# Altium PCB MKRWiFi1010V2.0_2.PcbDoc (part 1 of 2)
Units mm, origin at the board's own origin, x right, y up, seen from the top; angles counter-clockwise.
Board outline 61.5 x 25 mm, 4 copper layers (Top, PWR, MID, Bottom), stack 0.925 mm thick; 118 components, 85 nets, 439 pads, 197 vias.
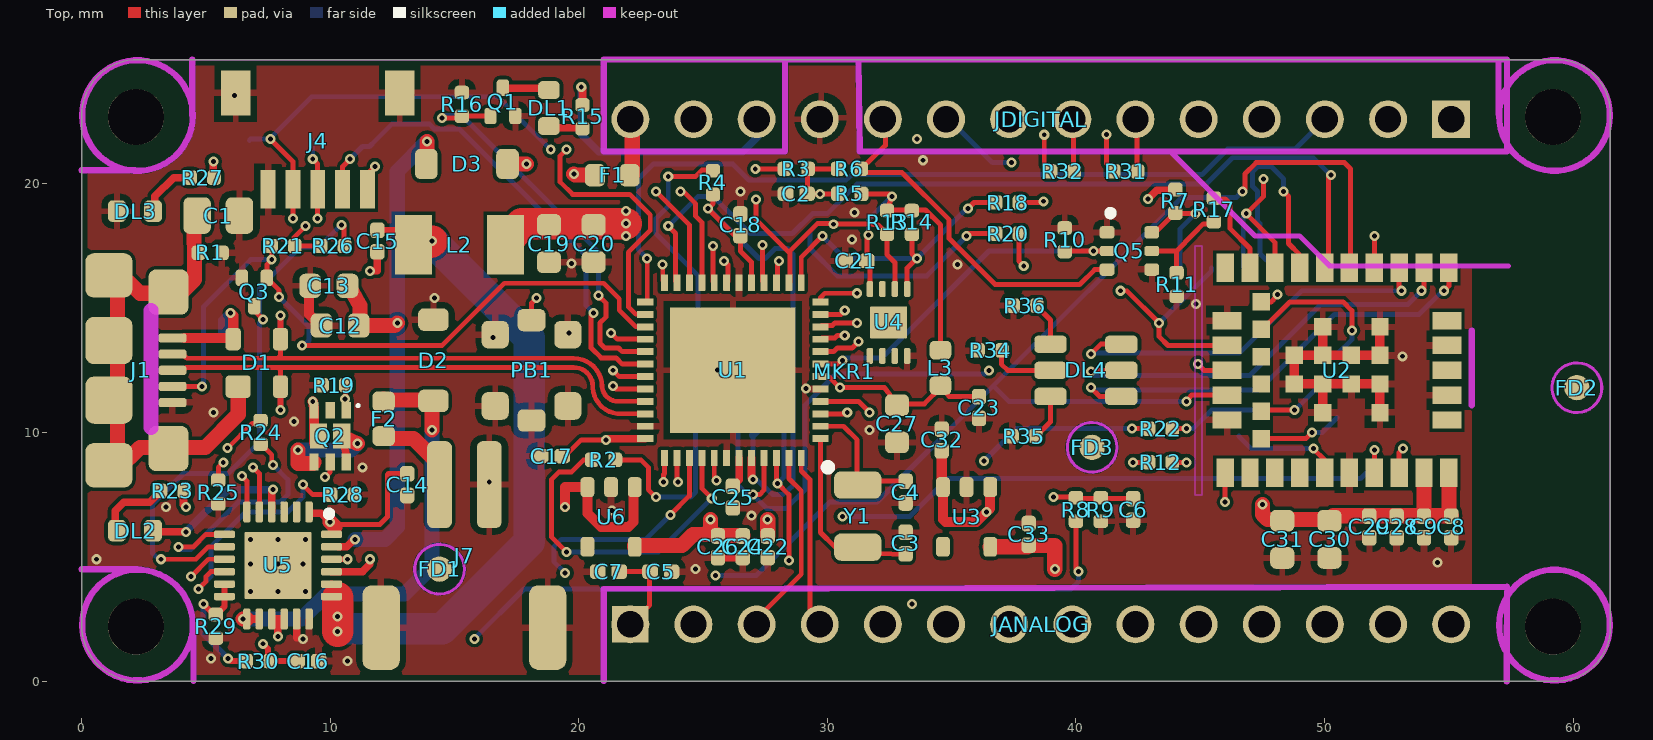
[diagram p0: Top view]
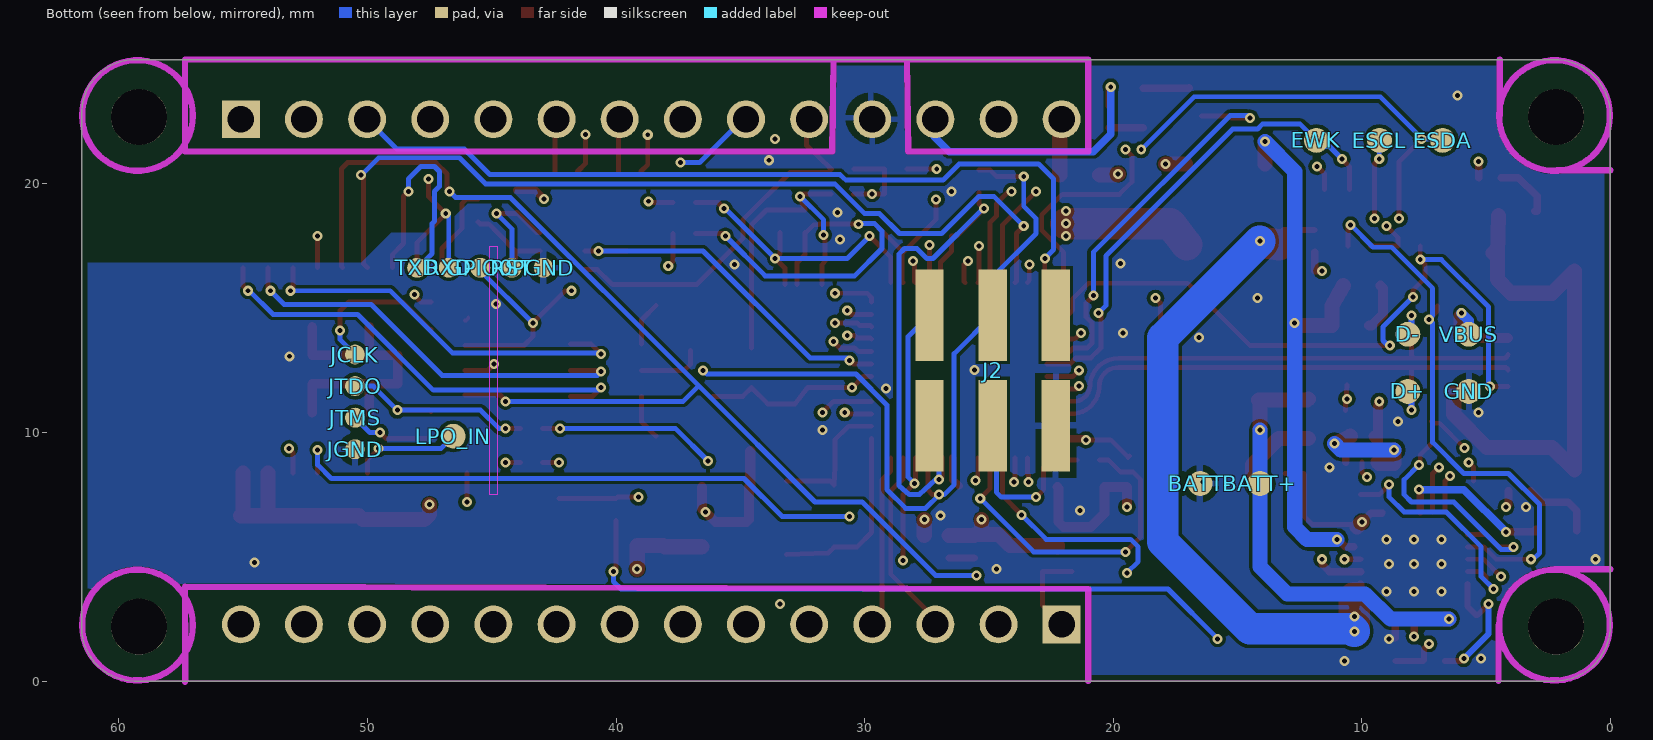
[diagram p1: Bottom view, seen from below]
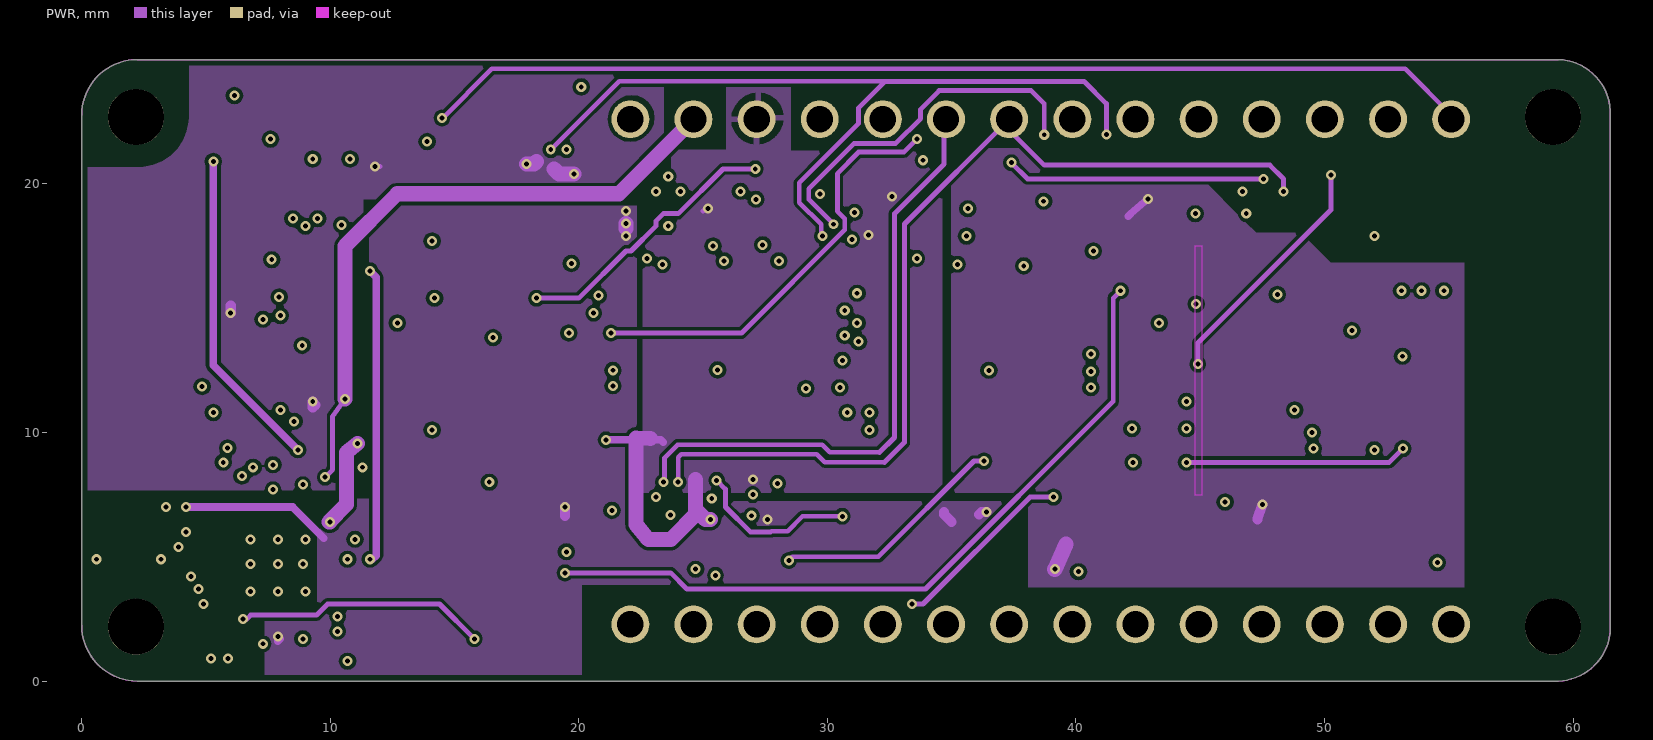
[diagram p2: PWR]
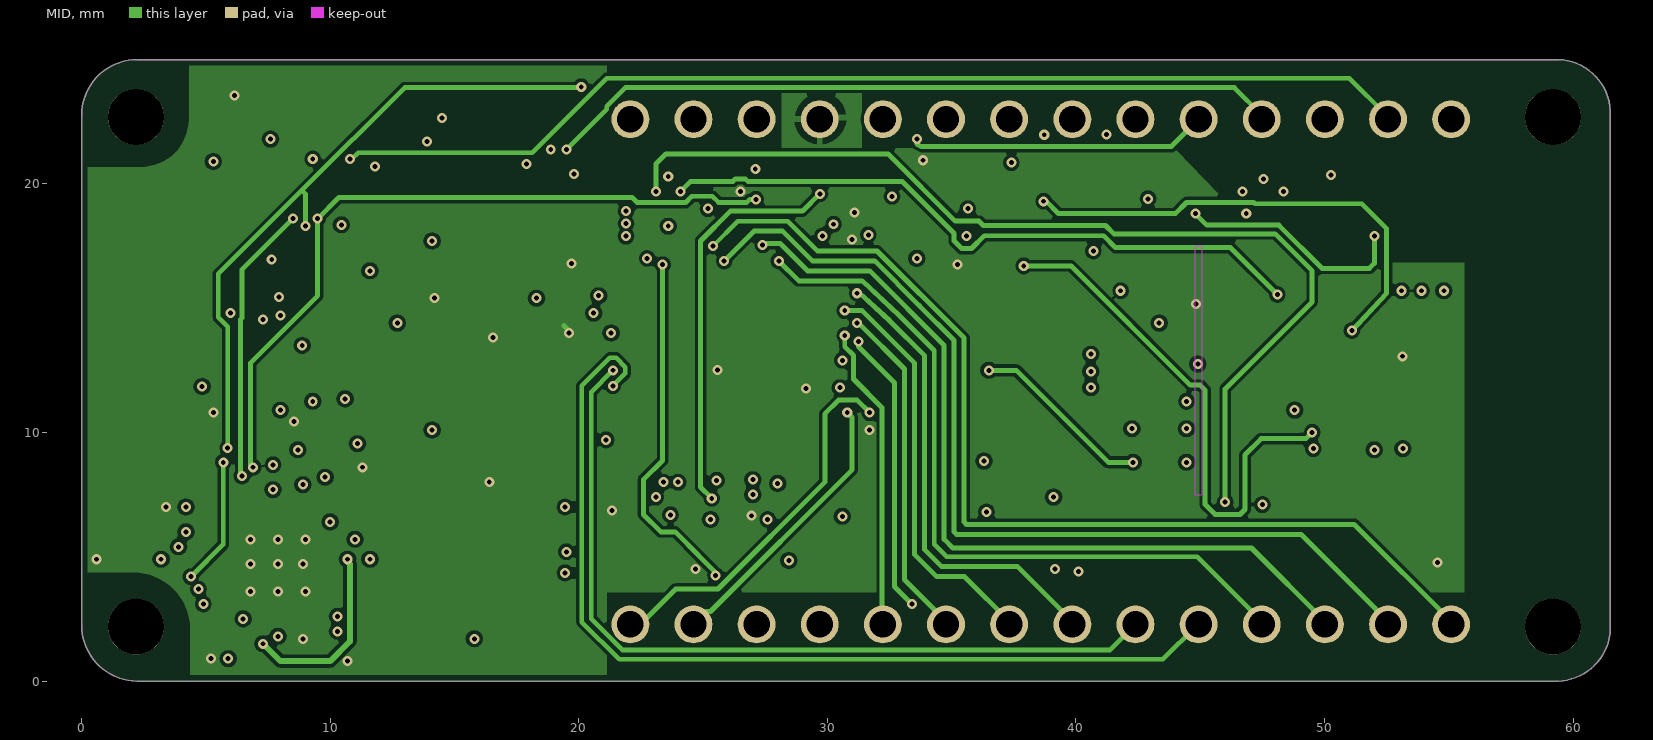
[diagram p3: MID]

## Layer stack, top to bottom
Top Solder: solder mask 0.0102, Solder Resist, Dk 3.5
Top: signal copper 0.035
Dielectric 1: core 0.2, FR-4, Dk 4.8
PWR: signal copper 0.0175
Dielectric3: core 0.3, FR-4, Dk 4.8
MID: signal copper 0.0175
Dielectric2: dielectric 0.32, FR-4, Dk 4.8
Bottom: signal copper 0.035
Bottom Solder: solder mask 0.0102, Solder Resist, Dk 3.5

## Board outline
61.5,2.25 cw(c59.325,2.175) 59.4,0 2.25,0 cw(c2.25,2.25) 0,2.25 0,22.75 cw(c2.25,22.75) 2.25,25 59.4,25 cw(c59.325,22.825) 61.5,22.75

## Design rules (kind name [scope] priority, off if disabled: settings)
BoardOutlineClearance mdCopperDimension [not IsKeepOut] p1: gap=0.254 ignorepadtopadclearanceinfootprint=FALSE except(0: Arc-SplitContinuation Track-SplitContinuation SMDPad-SplitContinuation THPad-SplitContinuation Via-SplitContinuation Fill-SplitContinuation Poly-SplitContinuation Region-SplitContinuation Text-SplitContinuation)
Clearance Clearance_for_PolygonClass_Isolate_0 [InPolygonClass('Isolate_0')] p1 off: gap=0 ignorepadtopadclearanceinfootprint=FALSE except(0.254: Poly-Hole)
Clearance Clearance_for_PolygonClass_Isolate_3.94 [InPolygonClass('Isolate_3.94')] p2 off: gap=0 ignorepadtopadclearanceinfootprint=FALSE except(0.1: Arc-Poly Track-Poly SMDPad-Poly THPad-Poly Via-Poly Fill-Poly Poly-Poly Poly-Region Poly-Text; 0.254: Poly-Hole)
Clearance [not Keepout vs not Keepout] p3: gap=0.138 ignorepadtopadclearanceinfootprint=TRUE except(0.127: SMDPad-SMDPad SMDPad-THPad SMDPad-Via THPad-THPad THPad-Via Via-Via)
Clearance "Clearance (Same Net)" [All] p4: gap=0 ignorepadtopadclearanceinfootprint=TRUE
Clearance Clearance_for_NetClass_usb [InNetClass('usb') vs InNetClass('usb')] p5: gap=0.127 ignorepadtopadclearanceinfootprint=FALSE
HoleSize HoleSize_For_NetClass_usb [InNetClass('usb')] p1: absolutevalues=TRUE maxlimit=0.19 minlimit=0.19 maxpercent=80.000 minpercent=20.000
HoleSize [All] p2: absolutevalues=TRUE maxlimit=2540 minlimit=0.195 maxpercent=80.000 minpercent=20.000
HoleToHoleClearance mdDrill [not HasFootprint('PINHD-1X14-MKR-5V-M/F') and not HasFootprint('PINHD-1X14-MKR-AREF-M/F') vs HasFootprint('MKRBOARD-Footprint-1')] p1: gap=0.203 allowstackedmicrovias=TRUE
MinimumSolderMaskSliver [All] p1 off: minsoldermaskwidth=0.254
PasteMaskExpansion Expansion_SMDPaste_OFF [InPadClass('All Pads')] p1: expansion=0
PasteMaskExpansion mlMinCreamFrame [All] p2: expansion=0
PolygonConnect PolygonConnect_For_PolygonThermal_ON_Width100000_Gap100000 [InPolygonClass('PolygonThermal_ON_Width100000_Gap100000') vs Not IsVia] p1: connectstyle=Relief reliefconductorwidth=0.254 reliefentries=4 polygonreliefangle="90 Angle" airgapwidth=0.254
PolygonConnect PolygonConnect_For_PolygonThermal_ON_Width98400_Gap100000 [InPolygonClass('PolygonThermal_ON_Width98400_Gap100000') vs Not IsVia] p2: connectstyle=Relief reliefconductorwidth=0.25 reliefentries=4 polygonreliefangle="90 Angle" airgapwidth=0.254
PolygonConnect ThermalVias [IsVia] p3: connectstyle=Direct reliefconductorwidth=0.254 reliefentries=4 polygonreliefangle="90 Angle" airgapwidth=0.254
PolygonConnect [All] p4: connectstyle=Direct reliefconductorwidth=0.254 reliefentries=4 polygonreliefangle="90 Angle" airgapwidth=0.254
RoomDefinition MKRWiFi1010V2.0_0 [InComponentClass('MKRWiFi1010V2.0_0')] p1 off: confinementstyle=ConfineIn formatcopy=TRUE lockcomponents=FALSE outline -1.651,-0.381 75.311,-0.381 75.311,63.627 -1.651,63.627
RoomDefinition MKRWiFi1010V2.0_1 [InComponentClass('MKRWiFi1010V2.0_1')] p2 off: confinementstyle=ConfineIn formatcopy=TRUE lockcomponents=FALSE outline 0.508,-0.254 61.595,-0.254 61.595,22.225 0.508,22.225
RoutingVias [All] p1: holewidth=0.195 width=0.398 viastyle="Through Hole" minholewidth=0.195 minwidth=0.398 maxholewidth=2.54 maxwidth=2.54
SilkToSolderMaskClearance [IsPad] p1 off: minsilkscreentomaskgap=0.254 clearancetoexposedcopper=TRUE
SolderMaskExpansion Expansion_SMDSolder_OFF [InPadClass('SMDSolder_OFF')] p1: expansion=0 istentingtop=FALSE
SolderMaskExpansion mlMinStopFrame [All] p2: expansion=0.102 istentingtop=FALSE
Width Width_For_NetClass_usb [InNetClass('usb')] p1: maxlimit=0.254 minlimit=0.19 preferedwidth=0.19
Width [All] p2: maxlimit=254 minlimit=0.152 preferedwidth=0.152
25 further rules are at their usual default settings.

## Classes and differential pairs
component class MKRWiFi1010V2.0_1: BATT+ BATT- C8 C9 C12 C13 C14 C15 C16 C17 C18 C19 C20 C21 C22 C23 C24 C25 C26 C27 C28 C29 C30 C31 C32 C33 D2 D3 DL2 DL3 F2 FD1 FD2 FD3 J7 L2 L3 Q2 Q3 R19 R21 R23 R24 R25 R26 R27 R28 R29 R30 U3 U5 U6
component class MKRWiFi1010V2.0_0: C1 C2 C3 C4 C5 C6 C7 D1 D+ D- DL1 DL4 ESCL ESDA EWK F1 GND GPIO0 J1 J2 J4 JANALOG JCLK JDIGITAL JGND JTDO JTMS LPO_IN MKR1 PB1 PGND Q1 Q5 R1 R2 R3 R4 R5 R6 R7 R8 R9 R10 R11 R12 R13 R14 R15 R16 R17 R18 R20 R22 R31 R32 R34 R35 R36 RST RXD TXD U1 U2 U4 VBUS Y1
polygon class PolygonThermal_ON_Width100000_Gap100000: Polygon_1_Net_+3V8 Polygon_1_Net_+5V Polygon_1_Net_GND Polygon_2_Net_GND Polygon_3_Net_GND
polygon class PolygonThermal_ON_Width98400_Gap100000: Polygon_1_Net_+3V3 Polygon_1_Net_+3V3D

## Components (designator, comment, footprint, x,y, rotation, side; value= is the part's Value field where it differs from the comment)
BATT+ "CMP-018-0005-A.3" TP-1.00MM 14.1,7.945 r180 bottom
BATT- "CMP-018-0005-A.3" TP-1.00MM 16.505,7.946 r180 bottom
C1 "C0805C472KDRACTU" CAP-0805 5.5,18.725 r0 top value=4.7nF
C2 "C0402C104K8PACTU" CAP-0402 28.75,19.6 r0 top value=100nF
C3 "C0402C200J5GACTU" CAP-0402 33.15,5.55 r90 top value=20pF
C4 "C0402C200J5GACTU" CAP-0402 33.15,7.6 r270 top value=20pF
C5 "GRM155R60J475ME47D" CAP-0402 23.3,4.4 r180 top value=4.7µF
C6 "C0402C104K8PACTU" CAP-0402 42.3,6.9 r90 top value=100nF
C7 "C0402C104K8PACTU" CAP-0402 21.2,4.4 r0 top value=100nF
C8 "C0402C104K8PACTU" CAP-0402 55.1,6.201 r90 top value=100nF
C9 "C0402C104K8PACTU" CAP-0402 54,6.201 r270 top value=100nF
C12 "GRM188R61E106MA73J" CAP-0603 10.4,14.3 r0 top value=10µF
C13 "GRM188R61E106MA73J" CAP-0603 9.95,15.901 r0 top value=10µF
C14 "C0402C105K4PACTU" CAP-0402 13.1,7.901 r270 top value=1µF
C15 "GRM155R61H473KE14D" CAP-0402 11.9,17.701 r90 top value=47nF
C16 "GRM155R60J475ME47D" CAP-0402 9.1,0.801 r0 top value=4.7µF
C17 "C0402C104K8PACTU" CAP-0402 18.9,9.051 r0 top value=100nF
C18 "C0402C104K8PACTU" CAP-0402 26.5,18.351 r270 top value=100nF
C19 "GRM188R61E106MA73J" CAP-0603 18.8,17.6 r90 top value=10µF
C20 "GRM188R61E106MA73J" CAP-0603 20.6,17.601 r90 top value=10µF
C21 "C0402C104K8PACTU" CAP-0402 31.15,16.901 r0 top value=100nF
C22 "C0402C105K4PACTU" CAP-0402 27.6,5.401 r90 top value=1µF
C23 "C0402C104K8PACTU" CAP-0402 36.1,11.001 r270 top value=100nF
C24 "C0402C104K8PACTU" CAP-0402 26.6,5.401 r90 top value=100nF
C25 "C0402C105K4PACTU" CAP-0402 26.2,7.401 r270 top value=1µF
C26 "C0402C105K4PACTU" CAP-0402 25.6,5.401 r90 top value=1µF
C27 "GRM188R6YA475KE15D" CAP-0603 32.8,10.351 r270 top value=4.7µF
C28 "C0402C104K8PACTU" CAP-0402 52.9,6.201 r270 top value=100nF
C29 "C0402C104K8PACTU" CAP-0402 51.8,6.201 r90 top value=100nF
C30 "06035G104ZAT4A" CAP-0603 50.2,5.701 r270 top value=100nF
C31 "06035G104ZAT4A" CAP-0603 48.3,5.701 r90 top value=100nF
C32 "C0402C105K4PACTU" CAP-0402 34.6,9.701 r270 top value=1µF
C33 "C0402C105K4PACTU" CAP-0402 38.1,5.901 r270 top value=1µF
D1 "Diode TVS array" SOT190P230X110-4N 7.05,12.8 r0 top
D2 "PMEG6020AELRX" SOD123-1 14.15,12.905 r90 top
D3 "PMEG6020AELRX" SOD123-1 15.5,20.801 r180 top
D+ "CMP-018-0005-A.3" TP-1.00MM 8.15,11.65 r180 bottom
D- "CMP-018-0005-A.3" TP-1.00MM 8.15,13.95 r180 bottom
DL1 "KPT-1608YC" LEDC1608X80N-AK 18.8,23.05 r270 top
DL2 "KPT-1608SECK" LEDC1608X80N-AK 2.15,6.051 r180 top
DL3 "HSMG-C190" LEDC1608X80N-AK 2.15,18.901 r0 top
DL4 "LTRBGFSF-ABCB-QKYO" RGBLED 40.4,12.5 r180 top
ESCL "CMP-018-0005-A.3" TP-1.00MM 9.29,21.75 r180 bottom
ESDA "CMP-018-0005-A.3" TP-1.00MM 6.75,21.75 r180 bottom
EWK "CMP-018-0005-A.3" TP-1.00MM 11.83,21.75 r180 bottom
F1 "MF-FSMF050X-2" 0603 21.35,20.35 r180 top
F2 "MF-FSMF050X-2" 0603 12.15,10.551 r90 top
FD1 "Fiducial mark 1.5mm" FIDUCIAL-1.5 14.4,4.501 r0 top
FD2 "Fiducial mark 1.5mm" FIDUCIAL-1.5 60.15,11.801 r0 top
FD3 "Fiducial mark 1.5mm" FIDUCIAL-1.5 40.65,9.401 r0 top
GND "CMP-018-0005-A.3" TP-1.00MM 5.7,11.65 r180 bottom
GPIO0 "CMP-018-0004-A.4" TP-0.8MM 45.46,16.625 r180 bottom
J1 "ZX62-AB-5PA(31)" ZX62-AB-5PA 1.1,12.5 r270 top
J2 "PHD-2X03-DNP" PHD-2X03-Footprint-1 24.85,12.5 r180 bottom
J4 "21TW-287" SM05B-SRSS-TB 9.5,22.2 r180 top
J7 "19TW-108" JST-S2B-PH-SM4-TB 15.4,4.951 r0 top
JANALOG "21TW-332" 21TW-332-Footprint-1 22.074,2.279 r0 top
JCLK "CMP-018-0004-A.4" TP-0.8MM 50.5,13.135 r180 bottom
JDIGITAL "21TW-331" 21TW-331-Footprint-1 55.094,22.599 r0 top
JGND "CMP-018-0004-A.4" TP-0.8MM 50.5,9.325 r180 bottom
JTDO "CMP-018-0004-A.4" TP-0.8MM 50.5,11.865 r180 bottom
JTMS "CMP-018-0004-A.4" TP-0.8MM 50.5,10.595 r180 bottom
L2 "SRP4020TA-2R2M" SRP4020 15.2,17.551 r0 top
L3 "BLM18PG471SN1D" L-0603 34.55,12.601 r270 top
LPO_IN "CMP-018-0005-A.3" TP-1.00MM 46.55,9.85 r180 bottom
MKR1 "Symbol" MKR-NOOUTLINE -0.061,-0.061 r0 top locked
PB1 "PTS820J25KSMTRLFS" C&K_PTS820_NO_HOLES-1 18.1,12.5 r90 top
PGND "CMP-018-0004-A.4" TP-0.8MM 42.92,16.625 r180 bottom
Q1 "2N7002T-7-F" SOT523 16.95,23.3 r0 top
Q2 "SIA817EDJ-T1-GE3" SON65P205X205X75-8N-MWSD 10,9.851 r0 top
Q3 "2N7002T-7-F" SOT523 6.95,15.651 r180 top
Q5 "CMP-017-0012-A.3" SOT363 42.15,17.3 r270 top
R1 "CRCW04021M00JNED" RES-0402 5.175,17.225 r180 top value=1M
R2 "RC0402FR-0739RL" RES-0402 21,8.9 r180 top value=39
R3 "CRCW0402330RJNED" RES-0402 28.75,20.6 r0 top value=330
R4 "CRCW04021K00FKEDC" RES-0402 25.4,20.05 r270 top value=1k
R5 "CRCW040210K0FKED" RES-0402 30.9,19.6 r0 top value=10k
R6 "CRCW0402330RJNED" RES-0402 30.887,20.6 r0 top value=330
R7 "CRCW040210K0FKED" RES-0402 44,19.3 r90 top value=10k
R8 "CRCW0402330KJNED" RES-0402 40,6.9 r270 top value=330k
R9 "CRCW04021M20JNED" RES-0402 41,6.9 r90 top value=1.2M
R10 "CRCW0402100KFKEDC" RES-0402 39.55,17.75 r90 top value=100k
R11 "CRCW0402100KFKEDC" RES-0402 44.05,15.95 r270 top value=100k
R12 "CRCW04020000Z0EDC" RES-0402 43.4,8.8 r0 top value=0
R13 "RC0402FR-074K7L" RES-0402 32.4,18.45 r90 top value=4.7k
R14 "RC0402FR-074K7L" RES-0402 33.4,18.45 r90 top value=4.7k
R15 "CRCW0402330RJNED" RES-0402 20.15,22.7 r270 top value=330
R16 "CRCW0402100KFKEDC" RES-0402 15.3,23.2 r270 top value=100k
R17 "CRCW04020000Z0EDC" RES-0402 45.55,18.95 r270 top value=0
R18 "CRCW04020000Z0EDC" RES-0402 37.25,19.25 r180 top value=0
R19 "CRCW0402100KFKEDC" RES-0402 10.15,11.901 r0 top value=100k
R20 "CRCW04020000Z0EDC" RES-0402 37.25,18 r180 top value=0
R21 "CRCW040210K0FKED" RES-0402 8.1,17.501 r180 top value=10k
R22 "CRCW04020000Z0EDC" RES-0402 43.4,10.15 r0 top value=0
R23 "CRCW0402330RJNED" RES-0402 3.65,7.651 r0 top value=330
R24 "CRCW040210K0FKED" RES-0402 7.2,10.001 r270 top value=10k
R25 "CRCW040210K0FKED" RES-0402 5.5,7.601 r90 top value=10k
R26 "CRCW040210K0FKED" RES-0402 10.1,17.501 r0 top value=10k
R27 "RC0402FR-07390RL" RES-0402 4.85,20.251 r0 top value=390
R28 "CRCW0402330RJNED" RES-0402 10.5,7.501 r0 top value=330
R29 "CRCW040210K0FKED" RES-0402 5.4,2.201 r90 top value=10k
R30 "CRCW04025K49FKED" RES-0402 7.1,0.801 r180 top value=5.49k
R31 "CRCW04020000Z0EDC" RES-0402 42,20.5 r180 top value=0
R32 "CRCW04020000Z0EDC" RES-0402 39.45,20.5 r180 top value=0
R34 "CRCW0402330RJNED" RES-0402 36.55,13.3 r0 top value=330
R35 "CRCW0402330RJNED" RES-0402 37.9,9.85 r0 top value=330
R36 "CRCW0402330RJNED" RES-0402 37.95,15.1 r0 top value=330
RST "CMP-018-0004-A.4" TP-0.8MM 44.19,16.625 r180 bottom
RXD "CMP-018-0004-A.4" TP-0.8MM 46.73,16.625 r180 bottom
TXD "CMP-018-0004-A.4" TP-0.8MM 48,16.625 r180 bottom
U1 "ATSAMD21G18A-48QFN-A.5" QFN48 26.2,12.5 r180 top
U2 "NINA-W102-00B" NINA-W102 50.95,12.5 r180 top
U3 "AP2112K-3.3TRG1-A.6" SOT25 35.6,6.601 r180 top
U4 "ATECC508A-MAH" UDFN8 32.462,14.425 r0 top
U5 "BQ24195LRGET-A.4" VQFN24 7.9,4.65 r0 top
U6 "AP2112K-3.3TRG1-A.6" SOT25 21.3,6.601 r180 top
VBUS "CMP-018-0005-A.3" TP-1.00MM 5.7,13.95 r90 bottom
Y1 "Q13FC1350000400" ABS07 31.225,6.637 r270 top

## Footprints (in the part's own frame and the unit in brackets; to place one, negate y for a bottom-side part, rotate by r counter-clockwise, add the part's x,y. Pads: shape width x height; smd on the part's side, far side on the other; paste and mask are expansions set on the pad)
21TW-331-Footprint-1 [mil]
  rect 60x60 / inner round 60 / far side rect 60x60 hole 41.73 paste-63.78 mask+0: 1(0,0)
  round 60 hole 41.73 paste-63.78 mask+0: 2(-100,0) 3(-200,0) 4(-300,0) 5(-400,0) 6(-500,0) 7(-600,0) 8(-700,0) 9(-800,0) 10(-900,0) 11(-1000,0) 12(-1100,0) 13(-1200,0) 14(-1300,0)
  body extent -1366,-52 54,50, height 335
21TW-332-Footprint-1 [mil]
  round 60 / inner round 60 / far side rect 60x60 hole 40.94 paste-63.78 mask+0: 1(0,0)
  round 60 hole 40.94 paste-63.78 mask+0: 2(100,0) 3(200,0) 4(300,0) 5(400,0) 6(500,0) 7(600,0) 8(700,0) 9(800,0) 10(900,0) 11(1000,0) 12(1100,0) 13(1200,0) 14(1300,0)
  body extent -66,-52 1354,51, height 335
0603 [mm] "Body 0603 imperial,1.6x0.8mm, IPC High Density"
  rrect50% 0.8x0.9 smd: 1(-0.7,0) 2(0.7,0)
  body extent -0.87,-0.48 0.87,0.48, height 0.23
ABS07 [mm]
  rrect50% 1.1x1.9 smd: 1(-1.25,0) 2(1.25,0)
  body extent -1.65,-0.83 1.65,0.83, height 0.9
C&K_PTS820_NO_HOLES-1 [mm]
  rrect46% 1.11x1.09 smd: 1(-1.434,1.46) 2(-1.434,-1.46) 3(1.434,1.46) 4(1.434,-1.46)
  rrect49% 0.89x1.12 smd: 5(-2.015,0) 6(2.015,0)
  body extent -2.25,-1.45 2.25,1.45, height 2
CAP-0402 [mm] "Chip Capacitor, 2-Leads, Body  0402 (in) 1005 (mm), IPC Medium Density"
  rrect52% 0.63x0.58 smd mask+0: 1(-0.435,0) 2(0.435,0)
  body extent -0.5,-0.25 0.5,0.25, height 0.5
CAP-0603 [mm] "Chip Capacitor, Body 0603 imperial,1.6x0.8mm, IPC High Density"
  rrect51% 0.87x0.97 smd mask+0: 1(-0.75,0) 2(0.75,0)
  body extent -0.8,-0.4 0.8,0.4, height 0.8
CAP-0805 [mm] "Chip Capacitor, Body 0805 imperial, 2.0x1.2mm, IPC Medium Density"
  rrect45% 1.11x1.47 smd mask+0: 1(-0.85,0) 2(0.85,0)
  body extent -1,-0.62 1,0.63, height 1.25
FIDUCIAL-1.5 [mil]
  rrect100% 40x40 smd paste-100: 1(0,0)
  Top keep-out circle w5: c0,0 r39.37
JST-S2B-PH-SM4-TB [mm]
  rrect50% 1x3.5 smd: 1(-1,2.95) 2(1,2.95)
  rrect50% 1.5x3.4 smd: 3(3.35,-2.8) 4(-3.35,-2.8)
  body extent -3.84,-4.43 4.06,4.17, height 5.5
L-0603 [mm] "Chip Inductor - Body 0603 imperial,1.6x0.8mm, IPC High Density"
  rrect51% 0.75x0.87 smd mask+0: 1(-0.71,0) 2(0.71,0)
  body extent -0.8,-0.4 0.8,0.4, height 0.8
LEDC1608X80N-AK [mm]
  rrect50% 0.72x0.87 smd: A(0.725,0) C(-0.725,0)
  body extent -0.8,-0.4 0.8,0.4, height 0.79
MKR-NOOUTLINE [mil]
  round 60 hole 41.73: 0(1671.45,92.13) 1(1771.45,92.13) 2(1871.45,92.13) 3(1971.45,92.13) 4(2071.45,92.13) 5(2171.45,92.13) 5V(871.45,892.13) 7(2071.45,892.13) 8(1971.45,892.13) 9(1871.45,892.13) 10(1771.45,892.13) 11(1671.45,892.13) 12(1571.45,892.13) 13(1471.45,892.13) 14(1371.45,892.13) A0(971.45,92.13) A1(1071.45,92.13) A2(1171.45,92.13) A3(1271.45,92.13) A4(1371.45,92.13) A5(1471.45,92.13) A6(1571.45,92.13) GND(1171.45,892.13) RST(1271.45,892.13) VCC(1071.45,892.13) VIN(971.45,892.13)
  rect 58.09x58.09 / inner round 60 / far side rect 58.09x58.09 hole 41.73: 6(2171.45,892.13)
  rect 58.09x58.09 / inner round 58.09 / far side rect 58.09x58.09 hole 41.73: AREF(871.45,92.13)
  round 88.58 hole 88.58 unplated: MH1(2332.68,88.58) MH2(2332.68,895.67) MH3(88.58,895.67) MH4(88.58,88.58)
NINA-W102 [mm]
  rect 0.7x1.15 smd: 1(4.95,4.125) 2(3.95,4.125) 3(2.95,4.125) 4(1.95,4.125) 5(0.95,4.125) 6(-0.05,4.125) 7(-1.05,4.125) 8(-2.05,4.125) 9(-3.05,4.125) 10(-4.05,4.125) 16(-4.05,-4.125) 17(-3.05,-4.125) 18(-2.05,-4.125) 19(-1.05,-4.125) 20(-0.05,-4.125) 21(0.95,-4.125) 22(1.95,-4.125) 23(2.95,-4.125) 24(3.95,-4.125) 25(4.95,-4.125)
  rect 1.15x0.7 smd: 11(-3.975,2) 12(-3.975,1) 13(-3.975,0) 14(-3.975,-1) 15(-3.975,-2) 26(4.875,-2) 27(4.875,-1) 28(4.875,0) 29(4.875,1) 30(4.875,2)
  rect 0.7x0.7 smd: 31(3.5,2.75) 32(3.5,1.65) 33(3.5,0.55) 34(3.5,-0.55) 35(3.5,-1.65) 36(3.5,-2.75) GND1(-1.28,1.7) GND2(-1.28,0.55) GND3(-1.28,-0.6) GND4(-1.28,-1.75) GND5(-0.13,0.55) GND6(-0.13,-0.6) GND7(1.02,1.7) GND8(1.02,0.55) GND9(1.02,-0.6) GND10(1.02,-1.75) GND11(2.17,0.55) GND12(2.17,-0.6)
  Keep-Out Layer region: 5.865,-5 6.165,-5 6.165,5 5.865,5
  body extent -8.27,-5.05 5.73,4.95, height 3.81
PHD-2X03-Footprint-1 [mil]
  rect 45x145 smd: 1(-100,-87.5) 2(-100,87.5) 3(0,-87.5) 4(0,87.5) 5(100,-87.5) 6(100,87.5)
QFN48 [mm]
  rrect3% 0.65x0.28 smd paste+0: 1(-3.525,2.75) 2(-3.525,2.25) 3(-3.525,1.75) 4(-3.525,1.25) 5(-3.525,0.75) 6(-3.525,0.25) 7(-3.525,-0.25) 8(-3.525,-0.75) 9(-3.525,-1.25) 10(-3.525,-1.75) 11(-3.525,-2.25) 12(-3.525,-2.75) 25(3.525,-2.75) 26(3.525,-2.25) 27(3.525,-1.75) 28(3.525,-1.25) 29(3.525,-0.75) 30(3.525,-0.25) 31(3.525,0.25) 32(3.525,0.75) 33(3.525,1.25) 34(3.525,1.75) 35(3.525,2.25) 36(3.525,2.75)
  rrect3% 0.28x0.65 smd paste+0: 13(-2.75,-3.525) 14(-2.25,-3.525) 15(-1.75,-3.525) 16(-1.25,-3.525) 17(-0.75,-3.525) 18(-0.25,-3.525) 19(0.25,-3.525) 20(0.75,-3.525) 21(1.25,-3.525) 22(1.75,-3.525) 23(2.25,-3.525) 24(2.75,-3.525) 37(2.75,3.525) 38(2.25,3.525) 39(1.75,3.525) 40(1.25,3.525) 41(0.75,3.525) 42(0.25,3.525) 43(-0.25,3.525) 44(-0.75,3.525) 45(-1.25,3.525) 46(-1.75,3.525) 47(-2.25,3.525) 48(-2.75,3.525)
  rect 5.05x5.05 smd: 49(0,0)
  silkscreen extent -3.97,3.76 -3.68,4.04, body extent -3.51,-3.51 3.51,3.51, height 0.78
RES-0402 [mm] "Chip Resistor, 2-Leads, Body  0402 (in) 1005 (mm), IPC Medium Density"
  rrect51% 0.55x0.58 smd mask+0: 1(-0.475,0) 2(0.475,0)
  body extent -0.5,-0.25 0.5,0.25, height 0.34
RGBLED [mm]
  rrect50% 1.3x0.7 smd: 1(-1.425,1.05) 2(-1.425,0) 3(-1.425,-1.05) 4(1.425,-1.05) 5(1.425,0) 6(1.425,1.05)
  body extent -1.8,-1.75 1.8,1.75, height 2.01
SM05B-SRSS-TB [mm]
  rect 0.6x1.55 smd: 1(-2,2.425) 2(-1,2.425) 3(0,2.425) 4(1,2.425) 5(2,2.425)
  rect 1.2x1.8 smd: SH1(-3.3,-1.45) SH2(3.3,-1.45)
  body extent -3.5,-2.15 3.5,2.8, height 2.9
SOD123-1 [mm]
  rrect50% 0.91x1.22 smd: A(1.635,0) C(-1.635,0)
  body extent -1.78,-0.78 1.92,0.82, height 1.27
SON65P205X205X75-8N-MWSD [mm]
  rect 0.37x0.67 smd: A(0.65,1.04) D(-0.65,1.04) G(0,-1.04) K(0.65,-1.04) NC(0,1.04) S(-0.65,-1.04)
  rect 0.7x1 smd: D2(-0.467,0) K2(0.467,0)
  silkscreen extent 1.08,1.18 1.17,1.27, body extent -1,-1 1,1, height 0.75
SOT25 [mil]
  rrect50% 21.65x31.5 smd: 1(-37.4,-47.24) 2(0,-47.24) 3(37.4,-47.24) 4(37.4,47.24) 5(-37.4,47.24)
  body extent -59,-44 59,50, height 43
SOT190P230X110-4N [mm]
  rrect33% 1.01x0.91 smd paste+0 mask+0: 1(-0.75,-0.955)
  rrect49% 0.61x0.91 smd paste+0 mask+0: 2(0.95,-0.955) 3(0.95,0.955) 4(-0.95,0.955)
  body extent -1.45,-1.15 1.45,1.15, height 1
SOT363 [mm]
  rrect50% 0.5x0.6 smd: 1(-0.75,-0.9) 3(0.75,-0.9) 4(0.75,0.9) 6(-0.75,0.9)
  rrect50% 0.4x0.6 smd: 2(0,-0.9) 5(0,0.9)
  silkscreen extent -1.62,-0.86 -1.42,-0.66, body extent -1.05,-1.15 1.05,1.15, height 1
SOT523 [mm]
  rrect50% 0.5x0.66 smd: D(0,0.57) G(-0.5,-0.57) S(0.5,-0.57)
  body extent -0.8,-0.8 0.8,0.8, height 0.8
SRP4020 [mm]
  rect 1.5x2.4 smd: 1(-1.85,0) 2(1.85,0)
  body extent -2.15,-2 2.15,2, height 1.9
TP-0.8MM [mil]
  rrect100% 31.5x31.5 smd paste-100: X(0,0)
TP-1.00MM [mm]
  rrect100% 1x1 smd paste-2.54: X(0,0)
UDFN8 [mm] "QFN, 8-Leads, Body 3.00x2.00mm, Pitch 0.50mm, Thermal Pad 1.30x1.50mm, IPC Medium Density"
  rrect54% 0.26x0.64 smd paste+0 mask+0: 1(-0.75,-1.345) 2(-0.25,-1.345) 3(0.25,-1.345) 4(0.75,-1.345) 5(0.75,1.345) 6(0.25,1.345) 7(-0.25,1.345) 8(-0.75,1.345)
  rrect8% 1.5x1.3 smd paste-1.5 mask+0: 9(0,0)
  body extent -1,-1.5 1,1.5, height 0.55
VQFN24 [mm]
  rrect50% 0.3x0.85 smd: 1(1.25,2.155) 2(0.75,2.155) 3(0.25,2.155) 4(-0.25,2.155) 5(-0.75,2.155) 6(-1.25,2.155) 13(-1.25,-2.155) 14(-0.75,-2.155) 15(-0.25,-2.155) 16(0.25,-2.155) 17(0.75,-2.155) 18(1.25,-2.155)
  rrect50% 0.85x0.3 smd: 7(-2.155,1.25) 8(-2.155,0.75) 9(-2.155,0.25) 10(-2.155,-0.25) 11(-2.155,-0.75) 12(-2.155,-1.25) 19(2.155,-1.25) 20(2.155,-0.75) 21(2.155,-0.25) 22(2.155,0.25) 23(2.155,0.75) 24(2.155,1.25)
  rrect5% 2.7x2.7 smd paste-2.718: EXP(0,0)
  silkscreen extent 1.95,1.98 2.15,2.18, body extent -2.05,-2.05 2.05,2.05, height 1
ZX62-AB-5PA [mm]
  rrect49% 0.37x1.11 smd paste+0 mask+0: 1(-1.3,2.56) 2(-0.65,2.56) 3(0,2.56) 4(0.65,2.56) 5(1.3,2.56)
  rrect37% 1.825x1.6 smd paste+0 mask+0: M1(-3.147,2.4) M4(3.147,2.4)
  rrect37% 1.78x1.9 smd paste+0 mask+0: M2(-3.82,0) M3(3.82,0)
  rrect37% 1.9x1.9 smd paste+0 mask+0: M5(-1.2,0) M6(1.2,0)
  body extent -4.4,-2.75 4.4,2.85, height 2.75

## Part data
BATT+ BATT- D+ D- ESCL ESDA EWK GND LPO_IN VBUS: library part UT0013-A.1, "Test point 1.00mm"
C1: library part C0059-A.3, "CAP CHIP 0805 4.7nF 1000V X7R 10%", Case Code (Imperial)=0805, Case Code (Metric)=2012, Dielectric=X7R, MANUFACTURER=KEMET, Tolerance=10%, Voltage=1kV
C2 C6 C7 C8 C9 C17 C18 C21 C23 C24 C28 C29: library part C0011-A.3, "CAP CHIP 0402 100nf 10V X5R 10%", Case Code (Imperial)=0402, Case Code (Metric)=1005, Dielectric=X5R, MANUFACTURER=KEMET, Manufacturer 2=AVX, Manufacturer Part Number 2=0402ZD104KAT2A, Tolerance=10%, Voltage=10V
C3 C4: library part C0027-A.3, "CAP CHIP 0402 20pF 50V C0G 5%", Case Code (Imperial)=0402, Case Code (Metric)=1005, Dielectric=C0G, MANUFACTURER=KEMET, Manufacturer 2=AVX, Manufacturer Part Number 2=04025A200JAT2A, Tolerance=5%, Voltage=50V
C5 C16: library part C0037-A.3, "CAP CHIP 0402 4.7uF 6V3 X5R 20%", Case Code (Imperial)=0402, Case Code (Metric)=1005, Dielectric=X5R, MANUFACTURER=Murata, Tolerance=20%, Voltage=6.3V
C12 C13 C19 C20: library part C0047-A.6, "CAP CHIP 0603 10uF 25V X5R 20%", Case Code (Imperial)=0603, Case Code (Metric)=1608, Dielectric=X5R, MANUFACTURER=Murata, Manufacturer 2=Samsung, Manufacturer Part Number 2=CL10A226MPCNUBE, Part Number=C1608X5R1A226MT000N, Tolerance=20%, Voltage=25V
C14 C22 C25 C26 C32 C33: library part C0018-A.3, "CAP CHIP 0402 1uF 16V X5R 10%", Case Code (Imperial)=0402, Case Code (Metric)=1005, Dielectric=X5R, MANUFACTURER=KEMET, Manufacturer 2=AVX, Manufacturer Part Number 2=0402YD105KAT2A, Tolerance=10%, Voltage=16V
C15: library part C0036-A.3, "CAP CHIP 0402 47nF 50V X5R 10%", Case Code (Imperial)=0402, Case Code (Metric)=1005, Dielectric=X5R, MANUFACTURER=Murata, Tolerance=10%, Voltage=50V
C27: library part C0055-A.3, "CAP CHIP 0603 4.7uF 35V X5R 10%", Case Code (Imperial)=0603, Case Code (Metric)=1608, Dielectric=X5R, MANUFACTURER=Murata, Tolerance=10%, Voltage=35V
C30 C31: library part C0041-A.3, "CAP CHIP 0603 100nF 50V Y5V -20/+80%", Case Code (Imperial)=0603, Case Code (Metric)=1608, Dielectric=Y5V, MANUFACTURER=AVX, Manufacturer Part Number 2=06035G104ZAT2A, Tolerance='-20%/+80%, Voltage=50V
D1: library part D0025-A.2, "TVS ARRAY 4LIN.8kV 1pF SOT143B", MANUFACTURER=Nexperia, Part Number=PRTR5V0U2X,215
D2 D3: library part D0026-A.2, "DIODE SCHOTTKY SMD 1A 40V SOD123FL", MANUFACTURER=Nexperia
DL1: library part L0008-A.2, "LED SMD 0603 GIA588   8mcd 120^", MANUFACTURER=Kingbright
DL2: library part L0006-A.2, "LED SMD 0603 ORANGE601 250mcd 120^", MANUFACTURER=Kingbright
DL3: library part L0009-A.2, "LED SMD 0603 GREEN/568 15mcd 120^", MANUFACTURER=Broadcom
DL4: library part L0015-A.2, "LED SMDPLCC6 RGB 625-530-460nm", MANUFACTURER=OSRAM
F1 F2: library part P0000-A.2, "PTC SMD 0603 RESET FUSE 6V 0.5A", Current=500mA, MANUFACTURER=Bourns, Voltage=40V
FD1 FD2 FD3: library part UT0000-A.1
GPIO0 JCLK JGND JTDO JTMS PGND RST RXD TXD: library part UT0012-A.1, "Test point 0.8mm"
J1: library part J0039-A.2, "CONN USB MICRO F/90^ SMD TipoAB 5x1", MANUFACTURER=Hirose
J2: library part J0000-A.2, "CONN SMD 2X03, DNP", Part Number=-
J4: library part J0034-A.1, "CONN HEADER SMD R/A 5POS 1MM WIRE-BOARD"
J7: library part J0060-A.1, "CONN p2mm SMD M/90 2v S2B-PH.."
JANALOG: library part J0048-A.2, "CONN STRIP F/M 14x1 PITCH 2.54 MKR SHIELD AREF"
JDIGITAL: library part J0047-A.2, "CONN STRIP F/M 14x1 PITCH 2.54 MKR SHIELD 5V"
L2: library part I0017-A.3, "IND FIXED 2.2UH 4A 61 MOHM SMD", Current=4A, MANUFACTURER=Bourns
L3: library part I0006-A.2, "FERRITE SMD 0603 470R 1A 0.2R", Case Code (Imperial)=0603, Case Code (Metric)=1608, Current=1A, DC Resistance (DCR)=200mR, MANUFACTURER=Murata, Max Operating Temperature=125°C, Min Operating Temperature=-55°C, Package Quantity=1, Test Frequency=100MHz, Tolerance=25%
MKR1: library part UT0007-A.1, "MKR board without outline"
PB1: library part B0006-A.4, "PUSHBUTTON SMD PTS820 NO HOLES", Color=Black, MANUFACTURER=C&K, Max Operating Temperature=85°C, Min Operating Temperature=-40°C
Q1 Q3: library part T0003-A.1, "MOSFET N-CH 60V 115mA SOT523", MANUFACTURER="Diodes Inc."
Q2: library part T0010-A.1, "MOSFET P-CH 30V 4,5A 65mR SC70-6"
Q5: library part T0012-A.1, "MOSFET N-CH 2x 60V 0.32A SOT363", Part Number=BSS138PS
R1: library part R0006-A.3, "RES CHIP 0402 1M 5% 1/16W", Case Code (Imperial)=0402, Case Code (Metric)=1005, Manufacturer 2=Panasonic, Manufacturer Part Number 2=ERJ-2GEJ105X, Power=63mW, Tolerance=5%
R2: library part R0005-A.3, "RES CHIP 0402 39R 1% 1/16W", Case Code (Imperial)=0402, Case Code (Metric)=1005, MANUFACTURER=Yageo, Power=63mW, Tolerance=1%
R3 R6 R15 R23 R28 R34 R35 R36: library part R0017-A.3, "RES CHIP 0402 330R 5% 1/16W", Case Code (Imperial)=0402, Case Code (Metric)=1005, MANUFACTURER=Vishay, Manufacturer 2=Panasonic, Manufacturer Part Number 2=ERJ-2GEJ331X, Power=63mW, Tolerance=5%
R4: library part R0007-A.3, "RES CHIP 0402 1K 1% 1/16W", Case Code (Imperial)=0402, Case Code (Metric)=1005, MANUFACTURER=Vishay, Manufacturer 2=Panasonic, Manufacturer Part Number 2=ERJ-2RKF1001X, Power=63mW, Tolerance=1%
R5 R7 R21 R24 R25 R26 R29: library part R0003-A.3, "RES CHIP 0402 10K 1% 1/16W", Case Code (Imperial)=0402, Case Code (Metric)=1005, MANUFACTURER=Vishay, Manufacturer 2=Panasonic, Manufacturer Part Number 2=ERJ-2RKF1002X, Power=63mW, Tolerance=1%
R8: library part R0011-A.3, "RES CHIP 0402 330K 1% 1/16W", Case Code (Imperial)=0402, Case Code (Metric)=1005, MANUFACTURER=Vishay, Manufacturer 2=Panasonic, Manufacturer Part Number 2=ERJ-2GEJ334X, Power=63mW, Tolerance=5%
R9: library part R0022-A.3, "RES CHIP 0402 1M2 5% 1/16W", Case Code (Imperial)=0402, Case Code (Metric)=1005, MANUFACTURER=Vishay, Manufacturer 2=Panasonic, Manufacturer Part Number 2=ERJ-2GEJ125X, Power=63mW, Tolerance=5%
R10 R11 R16 R19: library part R0001-A.3, "RES CHIP 0402 100K 1% 1/16W", Case Code (Imperial)=0402, Case Code (Metric)=1005, MANUFACTURER=Vishay, Manufacturer 2=Panasonic, Manufacturer Part Number 2=ERJ-2RKF1003X, Power=63mW, Tolerance=1%
R12 R17 R18 R20 R22 R31 R32: library part R0000-A.3, "RES CHIP 0402 0R 1/16W", Case Code (Imperial)=0402, Case Code (Metric)=1005, MANUFACTURER=Vishay, Manufacturer 2=Panasonic, Manufacturer Part Number 2=ERJ-S020R00X, Power=63mW, Tolerance=J
R13 R14: library part R0013-A.3, "RES CHIP 0402 4K7 1% 1/16W", Case Code (Imperial)=0402, Case Code (Metric)=1005, MANUFACTURER=Yageo, Power=63mW, Tolerance=1%
R27: library part R0012-A.3, "RES CHIP 0402 390R 1% 1/16W", Case Code (Imperial)=0402, Case Code (Metric)=1005, MANUFACTURER=Yageo, Power=63mW, Tolerance=1%
R30: library part R0014-A.3, "RES CHIP 0402 5K49 1% 1/16W", Case Code (Imperial)=0402, Case Code (Metric)=1005, MANUFACTURER=Vishay, Manufacturer 2=Panasonic, Manufacturer Part Number 2=ERJ-2RKF5491X, Power=63mW, Tolerance=1%
U1: library part U0041-A.2, "IC ATSAMD21G18A-48QFN", MANUFACTURER=Microchip, Part Number=ATSAMD21G18A-48QFN
U2: library part M0002-A.2, "MODULE ESP32 WiFi/BLE", MANUFACTURER=UBlox
U3 U6: library part U0027-A.2, "IC V-REG LDO 3V3 600mA +En  SOT25", MANUFACTURER="Diodes Inc", Part Number=AP2112K-3.3TRG1
U4: library part U0033-A.2, "IC CRYPTO PROC.256b  UDFN8", MANUFACTURER=Microchip
U5: library part U0044-A.3, "IC BATT.CHRG.CTRL. VQFN24", MANUFACTURER="Texas Instruments", Part Number=BQ24195LRGET
Y1: library part X0003-A.2, "CRYSTAL SMD 32,768K3,2x1,5H,9RoHS", Frequency=32.768kHz, Frequency Tolerance=20ppm, Load Capacitance=12.5pF, MANUFACTURER=Epson, Manufacturer 2="Geyer Electronic", Manufacturer Part Number 2="KX-327NHT 32,768K", Max Operating Temperature=85°C, Min Operating Temperature=-40°C, Series Resistance=70kR

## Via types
v1: diameter 0.403, hole 0.2, Top to Bottom, tented both sides, 183 vias
v2: diameter 0.398, hole 0.195, Top to Bottom, tented both sides, 14 vias

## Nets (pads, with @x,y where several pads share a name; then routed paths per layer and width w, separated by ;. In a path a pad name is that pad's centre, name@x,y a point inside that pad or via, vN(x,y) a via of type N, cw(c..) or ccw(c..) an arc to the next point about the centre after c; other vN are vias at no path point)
+3V3: C17.2 C18.2 C21.2 C24.2 C26.2 J2.1 JDIGITAL.12 L3.1 MKR1.VCC R4.2 R5.2 R13.2 R14.2 R15.1 R21.1 R24.1 R26.1 U1.17 U1.36 U1.44 U4.8 U6.5 | length 98.9
  Top w0.19: v2(5.875,9.375) 6.875,10.375 7.125,10.375 R24.1@7.2,10.45
  Top w0.2: v1(9,18.3) 8.55,17.85 8.55,17.5 R26.1@9.65,17.5 ; C17.2@19.35,9.05 19.4,9 20.1,9.7 v1(21.1,9.7) ; R4.2@25.4,19.65 25.4,19.2 v1(25.2,19) 26.3,17.9 26.5,17.9 26.5,17.3 26.95,16.85 U1.17@26.95,16.025 ; R5.2@31.35,19.6 32.5,19.6 v1(32.6,19.5) 32.4,18.95 33.95,18.95 34.55,18.35 L3.1@34.55,13.4 ; v1(31.65,17.95) 31.6,17.9 31.6,16.9 31.712,16.738 U4.8@31.712,15.95
  Top w0.305: v1(20.1,23.9) 20.15,23.85 R15.1@20.15,23.15 ; v1(21.1,9.7) 21.15,9.75 U1.36@22.675,9.75 ; U1.44@26.95,8.975 26.95,8.15 v1(27,8.1)
  Top w0.61: U6.5@22.25,5.401 22.25,5.45 24.15,5.45 24.6,5.9 25.1,5.9 ; v1(25.3,6.5) 25.3,6.1 25.1,5.9 ; C24.2@26.6,5.85 25.6,5.85 25.55,5.9 25.1,5.9
  PWR w0.2: 25,18.9 25.1,19 v1(25.2,19)
  PWR w0.305: v1(21.1,9.7) 23.3,9.7 23.4,9.6
  PWR w0.61: 22.875,9.75 22.3,9.775 22.3,6.3 22.7,5.8 22.8,5.7 23.7,5.7 24.8,6.8 ; 24.7,8.1 24.7,6.9 24.8,6.8 ; v1(25.3,6.5) 25.1,6.5 24.8,6.8
  MID w0.19: v2(5.875,9.375) 5.875,14.25 5.5,14.625 5.5,16.375 8.863,19.738 13,23.875 20,23.875 v1(20.1,23.9)
  MID w0.2: 8.863,19.738 9,19.6 v1(9,18.3)
  Bottom w0.19: v1(25.2,19) v1@25.25,19 ; v1(32.6,19.5) v1@32.625,19.5
  Bottom w0.2: v1@25.25,19 27.25,17 27.5,17 27.9,17.4 28.4,17.4 28.625,17.175 28.625,7.875 28.6,7.85 28.2,7.5 27.8,7.5 27.15,8.1 v1(27,8.1) J2.1@27,9.887 ; v1(31.65,17.95) 31.65,18.55 v1(32.6,19.5)
  Bottom w0.305: v1(20.1,23.9) 20.1,22 20.8,21.3 26.6,21.3 27.2,21.9 27.2,22.645 JDIGITAL.12@27.215,22.66 ; J2.1@27,9.887 J2.1@27.39,10.278
+3V3D: C8.2 C9.1 C28.1 C29.2 C30.1 C31.2 C33.2 R7.2 U2.9 U2.10 U3.5 | length 19.2
  Top w0.305: v1(42.9,19.4) 43.25,19.75 R7.2@44,19.75
  Top w0.406: C30.1@50.2,6.5 C30.1@50.35,6.65 ; C8.2@55,6.75 C8.2@55.1,6.65
  Top w0.61: U3.5@36.55,5.401 38.05,5.4 38.1,5.45 39.15,5.45 v1(39.15,4.5) ; v1(47.5,7.1) 47.5,6.7 47.7,6.5 48.3,6.5 C30.1@50.2,6.5 ; C30.1@50.35,6.65 51.8,6.65 52.9,6.65 C9.1@54,6.65 ; U2.9@54,8.375 C9.1@54,6.65 ; C8.2@55,6.75 U2.10@55,8.375 ; C8.2@55.1,6.65 C9.1@54,6.65
  PWR w0.305: 42.1,18.7 42.2,18.8 v1(42.9,19.4)
  PWR w0.406: 47.3,6.5 v1(47.5,7.1)
  PWR w0.61: v1(39.15,4.5) 39.6,5.5
+3V8: C19.2 C20.2 C22.2 C32.2 L2.2 R23.2 U3.1 U3.3 U5.15 U5.16 U6.1 U6.3 | length 27.9
  Top w0.305: R23.2@4.1,7.65 4.1,7.1 v1(4.2,7) ; U5.15@7.65,2.495 U5.16@8.15,2.495 8.095,2.495 7.9,2.3 v1(7.9,1.8)
  Top w0.406: v1(19.45,7) 19.45,7.8 U6.3@20.35,7.801 20.35,6.75 20.9,6.2 22,6.2 22.2,6.4 22.2,7.75 U6.1@22.25,7.801 ; C32.2@34.6,9.25 34.6,7.85 U3.3@34.65,7.801 34.65,6.5 34.75,6.4 36,6.4 v1(36.4,6.8) 36.55,6.95 U3.1@36.55,7.801
  Top w0.61: C22.2@27.6,5.85 v1(27.6,6.5)
  Top w1.27: L2.2@17.05,17.55 17.7,18.4 18.8,18.4 20.6,18.4 v1(21.9,18.4)
  PWR w0.305: v1(4.2,7) 8.5,7 9.75,5.75 ; v1(7.9,1.8) 7.9,1.6 v1@8,1.7
  PWR w0.406: 19.45,6.65 v1(19.45,7) ; 34.7,6.8 34.7,6.7 35,6.4 ; 36.1,6.7 36.2,6.8 v1(36.4,6.8)
  PWR w0.61: v1@21.9,18.2 v1(21.9,18.4)
  other v1: 21.9,17.9 21.9,18.9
